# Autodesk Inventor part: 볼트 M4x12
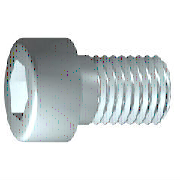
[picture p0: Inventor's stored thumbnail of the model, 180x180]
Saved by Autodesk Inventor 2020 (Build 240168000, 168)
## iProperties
IsCustomPart: 0
Created: 2012-02
Part Number: 볼트 M4x12
Material: 강철, 연강
Description: 6각머리 태핑 나사
Document SubType Name: Modeling
Standard: KS B 1003
Designer: mduedu
Standards Organization: KS
Language: ko-KR
Size Designation: M 4 x 12
Categories: <MemberInstance><Categories><Category DisplayName="조임쇠" InternalName="e4da775c-781d-43d5-af7c-5136215cf5a6" Mnemonic="FSTN"><Category DisplayName="볼트" InternalN
Density: 1 g/cm^3
Appearance: 강철
Author: mduedu
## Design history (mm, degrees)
sketch "스케치1"
  geometry: L1 (-1, 0)-(12, 0); L2 (12, 0)-(12, 2); L3 (12, 2)-(1.75, 2); L4 (1.75, 2)-(1.32, 2); L5 (1.32, 2)-(0, 2); L6 (0, 2)-(0, 3.5); L7 (0, 3.5)-(-4, 3.5); L8 (-4, 3.5)-(-4, 1.732); L9 (-4, 1.732)-(-2, 1.732); L10 (-2, 1.732)-(-1, 0); L11 (-7.2, 0)-(15.2, 0) reference; L12 (0, -0.7)-(0, 4.2) reference; L13 (1.75, 2)-(0, 2)
  constraints: 22 end point, 6 parallel, 2 collinear, 2 perpendicular, 1 horizontal, 1 point on line
  dimensions: "d1" = 10.25 distance from line of L3.end L2 (= GEL); "d2" = 0.42952 distance of L4.end L3.end (computed from GAL); "d3" = 4 distance between parallel lines of L8 L6 (= KOH); "d4" = 2 distance of L8.end L9.end (= INTI); "d5" = 60 deg angle of L10 L1; "d6" = 4 diameter of L3 L1 (= GD); "d7" = 4 diameter of L5 L1 (= BDM); "d8" = 3.4641 diameter of L9 L1 (= 1.1547 x SW); "d9" = 7 diameter of L7 L1 (= KOD); "d26" = 12 distance between parallel lines of L12 L2 (= NLG)
revolve "본체" sketch "스케치1" stored, may be unused: angle "d10" = 90 deg
sketch "스케치2"
  geometry: L1 (0, -4.9)-(0, 4.9) reference; L2 (-4.9, 0)-(4.9, 0) reference; L3 (1.732, 0)-(0.866, -1.5); L4 (0.866, -1.5)-(-0.866, -1.5); L5 (-0.866, -1.5)-(-1.732, 0); L6 (-1.732, 0)-(-0.866, 1.5); L7 (-0.866, 1.5)-(0.866, 1.5); L8 (0.866, 1.5)-(1.732, 0); 2 further points
  constraints: 12 end point, 1 coincident, 1 horizontal alignment, 1 point on line, 12 other
extrude "슬롯" join sketch "스케치2" stored distance "d11" = 10; taper "d12" = 0 deg
workplane "Work Plane1"
fillet "Fillet2" dims "d30" = 0.1 (= R)
body "Solid1"
fillet "모깎기1" dims "d17" = 0.4 (= RR)
feature "스레드" dims "d13" = 10.25 (= GEL), "d14" = 0
chamfer "모따기1" distance "d15" = 0.42941 (= -0.5 x SPD + 0.5 x GD); stored, may be unused: second distance "d16" = 0.42941 (= GUL), angle "d27" = 45 deg
other parameters: "GD" = 4 (= NND) [user parameter; used in 2 equation terms], "NLG" = 12 [user parameter; used in 1 equation term], "GEL" = 10.25 [user parameter; used in 2 equation terms], "KOD" = 7 [user parameter; used in 1 equation term], "KOH" = 4 [user parameter; used in 1 equation term], "INTI" = 2 [user parameter; used in 1 equation term], "GAL" = 0.42941 (= 0.61345 x PTC) [user parameter; used in 1 equation term], "GUL" = 0.42941 (= 0.61345 x PTC) [user parameter; used in 1 equation term], "BDM" = 4 (= NND) [user parameter; used in 1 equation term], "SW" = 3 [user parameter; used in 2 equation terms], "RR" = 0.4 [user parameter; used in 1 equation term], "SPD" = 3.14117 (= NND - 1.2269 x PTC) [user parameter; used in 1 equation term], "d19" = 0, "d28" = 0, "d29" = 0, "R" = 0.1 [user parameter; used in 1 equation term], "PHH" = 0.2 [user parameter], "GD1" = 3.14117 (= THREADDIA - 1.2269 x PTC) [user parameter], "THREADDIA" = 4 [user parameter; used in 1 equation term], "FAWI" = 45 deg [user parameter], "TPU" = 14.28571 (computed from PTC) [user parameter], "PTC" = 0.7 [user parameter; used in 5 equation terms], "NND" = 4 [user parameter; used in 3 equation terms], "TOA" = 30 deg [user parameter], "E0" = 3.465 (= 1.155 x SW) [user parameter]
